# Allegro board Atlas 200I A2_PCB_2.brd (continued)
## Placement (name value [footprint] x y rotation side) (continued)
R2108  0*  [SR0402-TA]  107.07 40.51 0 top
R2109  0*  [SR0402-TA]  124.64 45.32 180 top
R2110  0  [SR0402-TA]  123.83 45.32 0 top
R2111  0*  [SR0402-TA]  124.64 46.66 180 top
R2112  0  [SR0402-TA]  123.83 46.66 0 top
R2121  0  [SR0402-TA]  107.88 39.18 180 top
R2122  0*  [SR0402-TA]  107.07 39.18 0 top
R2123  0  [SR0402-TA]  108.03 46.98 180 top
R2124  0*  [SR0402-TA]  107.21 46.98 0 top
R2125  0  [SR0402-TA]  108.03 45.64 180 top
R2126  0*  [SR0402-TA]  107.21 45.64 0 top
R2127  0  [SR0402-TA]  111.82 36.78 270 top
R2128  0*  [SR0402-TA]  111.82 35.97 90 top
R2129  0  [SR0402-TA]  113.16 36.78 270 top
R2130  0*  [SR0402-TA]  113.16 35.97 90 top
R2131  0  [SR0402-TA]  114.13 52.15 180 top
R2132  0*  [SR0402-TA]  113.32 52.15 0 top
R2133  0  [SR0402-TA]  114.13 50.81 180 top
R2134  0*  [SR0402-TA]  113.32 50.81 0 top
R2135  0  [SR0402-TA]  107.95 51.3 180 top
R2136  0*  [SR0402-TA]  107.14 51.3 0 top
R2137  0  [SR0402-TA]  107.95 49.96 180 top
R2138  0*  [SR0402-TA]  107.14 49.96 0 top
R2139  0  [SR0402-TA]  100.58 45.9 270 top
R2140  0*  [SR0402-TA]  100.58 45.08 90 top
R2141  1k  [SR0402-TA]  100.58 42.98 270 top
R2142  4.7k*  [SR0402-TA]  100.58 42.16 270 top
R2143  10k  [SR0402-TA]  97.17 46.8 0 top
R2201  5.6k  [SR0402-TA]  154.08 33.68 180 top
R2202  11.3K  [SR0402-TA]  154.89 31.85 90 top
R2203  10k*  [SR0402-TA]  151 31.03 90 top
R2204  10k  [SR0402-TA]  164.24 17.12 180 top
R2205  5.6k  [SR0402-TA]  141.85 27.91 90 top
R2206  11.3K  [SR0402-TA]  141.85 26.24 90 top
R2207  10k  [SR0402-TA]  138.94 27.91 270 top
R2208  10k  [SR0402-TA]  147.75 13.03 270 top
R2209  0  [SR0402-TA]  203.62 154.95 0 top
R2210  0  [SR0402-TA]  203.62 155.86 0 top
R2211  0  [SR0402-TA]  203.62 153.12 0 top
R2212  0  [SR0402-TA]  203.62 152.2 0 top
R2213  5.6k  [SR0402-TA]  236.73 173.35 90 top
R2214  11.3K  [SR0402-TA]  237.62 173.35 270 top
R2215  10k  [SR0402-TA]  238.51 173.35 270 top
R2216  10k  [SR0402-TA]  235.46 172.85 180 top
R2217  10k*  [SR0402-TA]  238.51 176.66 90 top
R2218  0  [SR0402-TA]  203.62 159.67 0 top
R2219  0  [SR0402-TA]  203.62 160.59 0 top
R2220  0  [SR0402-TA]  150.71 23.42 0 top
R2221  0  [SR0402-TA]  150.71 24.33 0 top
R2222  0  [SR0402-TA]  165.73 22.58 270 top
R2223  0  [SR0402-TA]  166.65 22.58 270 top
R2224  0  [SR0402-TA]  168.93 22.6 270 top
R2225  0  [SR0402-TA]  168.02 22.6 270 top
R2226  0  [SR0402-TA]  152.76 19.2 0 top
R2227  0  [SR0402-TA]  152.76 20.12 0 top
R2228  0  [SR0402-TA]  152.76 17.07 0 top
R2229  0  [SR0402-TA]  152.76 17.98 0 top
R2230  0  [SR0402-TA]  150.71 21.3 0 top
R2231  0  [SR0402-TA]  150.71 22.21 0 top
R2301  27k  [SR0402-TA]  121.92 191.52 180 top
R2302  100  [SR0402-TA]  121.92 192.53 0 top
R2305  100  [SR0402-TA]  128.14 195.33 270 top
R2306  100  [SR0402-TA]  128.14 193.17 90 top
R2307  4.7k  [SR0402-TA]  129.03 193.17 270 top
R2308  1k*  [SR0402-TA]  121.92 196.6 0 top
R2309  0  [SR0402-TA]  121.92 193.55 180 top
R2310  47k  [SR0402-TA]  121.92 195.58 180 top
R2317  4.7k  [SR0402-TA]  129.03 195.33 90 top
R2401  27k  [SR0402-TA]  96.8 184.12 180 top
R2402  100  [SR0402-TA]  96.8 185.14 0 top
R2403  100  [SR0402-TA]  103 187.83 180 top
R2404  100  [SR0402-TA]  103 184.78 180 top
R2405  4.7k  [SR0402-TA]  103 185.8 0 top
R2406  1k*  [SR0402-TA]  96.77 189.86 0 top
R2407  0  [SR0402-TA]  96.77 186.82 180 top
R2408  47k  [SR0402-TA]  96.77 187.83 180 top
R2417  4.7k  [SR0402-TA]  103 186.82 0 top
R2501  1.1k  [SR0603-TB]  195.45 17.14 0 top
R2502  1.1k  [SR0603-TB]  195.94 15.26 90 top
R2503  0  [SR0402-TA]  195.58 18.41 180 top
R2504  0  [SR0402-TA]  197.99 18.41 0 top
R2505  2.2k*  [SR0402-TA]  188.85 6.32 180 top
R2506  1.1k  [SR0603-TB]  197.99 17.14 180 top
R2507  1.1k  [SR0603-TB]  197.33 15.26 90 top
R2508  100k*  [SR0402-TA]  197.03 13 90 top
R2509  100k*  [SR0402-TA]  196.17 13 90 top
R2510  100k  [SR0402-TA]  188.34 14.17 0 top
R2511  100k  [SR0402-TA]  186.56 16.23 0 top
R2512  1k  [SR0402-TA]  181.61 23.42 270 top
R2513  2.49k  [SR0603B]  184.53 23.11 180 top
R2514  10k  [SR0402-TA]  180.21 23.8 180 top
R2515  4.7k  [SR0402-TA]  182.63 24.94 90 top
R2516  560  [SR0603-TB]  184.61 24.38 0 top
R2517  100k  [SR0402-TA]  177.42 18.29 90 top
R2518  100k  [SR0402-TA]  186.56 17.12 180 top
R2519  560  [SR0603-TB]  189.99 20.62 0 top
R2520  4.7k  [SR0402-TA]  189.74 21.97 0 top
R2521  10k  [SR0402-TA]  187.43 19.18 180 top
R2522  2.49k  [SR0603B]  188.93 18.62 90 top
R2523  1k  [SR0402-TA]  187.43 18.29 180 top
R2524  0  [SR0402-TA]  208.84 19.02 270 top
R2525  0  [SR0402-TA]  209.91 19.05 270 top
R2526  2.2k*  [SR0402-TA]  206.63 13.21 180 top
R2613  33  [SR0402-TA]  21.62 130.5 0 top
R2614  33  [SR0402-TA]  21.62 129.59 0 top
R2615  33  [SR0402-TA]  23.5 122.02 0 top
R2616  33  [SR0402-TA]  23.5 122.94 0 top
R2617  33  [SR0402-TA]  21.62 125.65 0 top
R2618  33  [SR0402-TA]  21.62 126.57 0 top
R2623  49.9  [SR0402-TA]  23.52 128.57 0 top
R2624  49.9  [SR0402-TA]  23.52 131.52 0 top
R2625  49.9  [SR0402-TA]  23.52 124.64 0 top
R2626  49.9  [SR0402-TA]  23.52 127.58 0 top
R2627  49.9  [SR0402-TA]  25.41 121.13 0 top
R2628  49.9  [SR0402-TA]  25.41 123.95 0 top
R2642  33  [SR0402-TA]  16.51 134.37 90 top
R2643  33  [SR0402-TA]  17.42 134.37 90 top
R2646  49.9  [SR0402-TA]  15.49 135.99 90 top
R2647  49.9  [SR0402-TA]  18.44 135.99 90 top
R2701  0  [SR0402-TA]  40.26 24.76 90 top
R2702  0  [SR0402-TA]  39.4 24.76 90 top
R2703  4.7k*  [SR0402-TA]  45.72 23.37 180 top
R2704  4.7k*  [SR0402-TA]  45.72 24.99 180 top
R2705  4.7k*  [SR0402-TA]  45.72 22.1 180 top
R2706  4.7k  [SR0402-TA]  47.63 23.37 0 top
R2707  4.7k  [SR0402-TA]  47.63 22.1 0 top
R2708  4.7k  [SR0402-TA]  47.63 24.99 0 top
R2709  0  [SR0402-TA]  170.94 31.24 90 top
R2710  0  [SR0402-TA]  170.94 33.78 90 top
R2711  4.7k  [SR0402-TA]  168.78 31.29 270 top
R2712  4.7k  [SR0402-TA]  175.77 19.76 270 top
R2713  4.7k  [SR0402-TA]  167.51 31.29 270 top
R2714  4.7k  [SR0402-TA]  174.65 19.76 270 top
R2715  4.7k  [SR0402-TA]  166.24 31.29 270 top
R2716  4.7k  [SR0402-TA]  173.53 19.76 270 top
R2717  4.7k  [SR0402-TA]  164.97 31.29 270 top
R2718  4.7k  [SR0402-TA]  172.42 19.76 270 top
R2719  4.7k  [SR0402-TA]  179.58 31.29 90 top
R2720  4.7k  [SR0402-TA]  178.31 31.29 90 top
R2721  4.7k  [SR0402-TA]  177.04 31.29 90 top
R2722  4.7k  [SR0402-TA]  175.77 31.29 90 top
R2723  4.7k  [SR0402-TA]  174.5 31.29 90 top
R2724  4.7k  [SR0402-TA]  173.25 37.77 90 top
R2725  4.7k  [SR0402-TA]  174.14 37.77 90 top
R2726  4.7k  [SR0402-TA]  173.23 31.29 90 top
R2727  1k  [SR0402-TA]  168.78 29.13 90 top
R2728  1k  [SR0402-TA]  175.73 17.5 90 top
R2729  1k  [SR0402-TA]  167.51 29.13 90 top
R2730  1k  [SR0402-TA]  174.62 17.5 90 top
R2731  1k  [SR0402-TA]  166.24 29.13 90 top
R2732  1k  [SR0402-TA]  173.51 17.5 90 top
R2733  1k  [SR0402-TA]  164.97 29.13 90 top
R2734  1k  [SR0402-TA]  172.4 17.5 90 top
R2735  1k  [SR0402-TA]  179.58 33.83 270 top
R2736  1k  [SR0402-TA]  178.31 33.83 270 top
R2737  1k  [SR0402-TA]  177.04 33.83 270 top
R2738  1k  [SR0402-TA]  175.77 33.83 270 top
R2739  1k  [SR0402-TA]  174.5 33.83 270 top
R2740  1k  [SR0402-TA]  173.63 36.4 180 top
R2741  1k  [SR0402-TA]  175.46 38.23 180 top
R2742  1k  [SR0402-TA]  173.23 33.83 270 top
R2743  4.7k*  [SR0402-TA]  172.09 31.24 90 top
R2744  4.7k*  [SR0402-TA]  170.18 19.79 270 top
R2745  4.7k*  [SR0402-TA]  171.3 19.79 270 top
R2746  1k  [SR0402-TA]  171.29 17.5 90 top
R2747  1k  [SR0402-TA]  170.18 17.5 90 top
R2748  1k  [SR0402-TA]  171.96 33.83 270 top
R2749  4.7k  [SR0402-TA]  3.8 100.99 90 top
R2750  33  [SR0402-TA]  6.3 109.93 270 top
R2751  33  [SR0402-TA]  5.38 109.93 270 top
R2752  33  [SR0402-TA]  4.82 100.99 270 top
R2753  33  [SR0402-TA]  5.71 100.99 270 top
R2754  4.7k  [SR0402-TA]  133.78 76.75 90 top
R2755  4.7k  [SR0402-TA]  131.83 78.54 270 top
R2758  0  [SR0402-TA]  93.44 131.98 180 top
R2759  33  [SR0402-TA]  85.52 131.1 90 top
R2760  33  [SR0402-TA]  84.51 131.1 90 top
R2761  0  [SR0402-TA]  86.54 131.1 90 top
R2762  33  [SR0402-TA]  88.06 131.1 90 top
R2763  0  [SR0402-TA]  89.59 131.1 90 top
R2776  0  [SR0402-TA]  24.31 21.61 180 top
R2777  0  [SR0402-TA]  22.23 26.92 0 top
R2778  0  [SR0402-TA]  36.53 28.63 180 top
R2779  0  [SR0402-TA]  20.32 25.53 270 top
R2780  0*  [SR0402-TA]  20.32 27.66 270 top
R2781  1k*  [SR0402-TA]  22.23 28.07 0 top
R2782  33  [SR0402-TA]  24.26 28.07 0 top
R2783  33  [SR0402-TA]  41.02 27.43 270 top
R2784  4.7k*  [SR0402-TA]  40.01 27.43 90 top
R2801  33  [SR0402-TA]  188.6 49.4 0 top
R2802  33  [SR0402-TA]  190.63 39.75 180 top
R2803  4.7k*  [SR0402-TA]  195.96 59.05 270 top
R2804  4.7k  [SR0402-TA]  194.82 70.48 180 top
R2805  4.7k  [SR0402-TA]  193.29 59.16 90 top
R2806  33  [SR0402-TA]  194.69 59.44 0 top
R2807  33  [SR0402-TA]  192.91 38.76 0 top
R2808  33  [SR0402-TA]  188.6 50.55 0 top
R2809  4.7k*  [SR0402-TA]  190.63 54.61 180 top
R2810  4.7k*  [SR0402-TA]  192.02 59.16 90 top
R2811  200  [SR0402-TA]  205.74 31.37 0 top
R2812  33  [SR0402-TA]  207.14 56.51 270 top
R2813  33  [SR0402-TA]  199.01 56.54 270 top
R2814  150k  [SR0402-TA]  189.48 32.03 90 top
R2815  30k  [SR0402-TA]  189.48 34.39 90 top
R2816  10k  [SR0402-TA]  190.5 34.31 90 top
R2817  20k  [SR0402-TA]  190.5 32.03 90 top
R2818  10k  [SR0402-TA]  191.52 32.03 90 top
R2819  10k  [SR0402-TA]  191.52 34.31 90 top
R2820  10k  [SR0402-TA]  188.47 32.03 90 top
R2821  10k  [SR0402-TA]  188.47 34.39 90 top
R2822  10k  [SR0402-TA]  192.53 34.31 90 top
R2823  20k  [SR0402-TA]  192.53 32.03 90 top
R2824  10k  [SR0402-TA]  193.55 34.31 90 top
R2825  10k  [SR0402-TA]  193.55 32.03 90 top
R2826  0*  [SR0402-TA]  188.98 48.06 270 top
R2827  0  [SR0402-TA]  197.87 36.32 270 top
R2828  4.7k  [SR0402-TA]  186.44 45.72 180 top
R2829  4.7k*  [SR0402-TA]  188.34 45.72 0 top
R2830  4.7k  [SR0402-TA]  196.88 59.05 270 top
R2831  0  [SR0402-TA]  194.56 34.19 270 top
R2832  33  [SR0402-TA]  206.12 54.23 90 top
R2833  0  [SR0402-TA]  199.52 38.61 270 top
R2834  33  [SR0402-TA]  202.06 56.51 90 top
R2835  33  [SR0402-TA]  205.11 56.51 90 top
R2836  33  [SR0402-TA]  206.15 56.49 90 top
R2837  0  [SR0402-TA]  203.2 38.48 270 top
R2838  0  [SR0402-TA]  198.5 38.61 270 top
R2839  33  [SR0402-TA]  204.09 54.23 90 top
R2840  0  [SR0402-TA]  196.95 36.32 270 top
R2841  33  [SR0402-TA]  202.06 54.23 90 top
R2842  33  [SR0402-TA]  200.03 54.23 90 top
R2843  33  [SR0402-TA]  199.01 54.23 90 top
R2844  0  [SR0402-TA]  203.43 36.19 270 top
R2845  0  [SR0402-TA]  190.63 53.59 180 top
R2846  33  [SR0402-TA]  205.11 54.23 90 top
R2847  0  [SR0402-TA]  203.07 56.51 90 top
R2848  33  [SR0402-TA]  204.09 56.51 90 top
R2849  33  [SR0402-TA]  178.15 40.49 270 top
R2850  33  [SR0402-TA]  179.01 40.49 90 top
R2851  33  [SR0402-TA]  179.86 40.49 90 top
R2852  33  [SR0402-TA]  180.72 40.49 90 top
R2853  0  [SR0402-TA]  196.6 32.16 0 top
R2854  0  [SR0402-TA]  196.6 33.01 0 top
R2855  0  [SR0402-TA]  207.44 36.19 90 top
R2856  0  [SR0402-TA]  192.91 40.77 0 top
R2857  0  [SR0402-TA]  209.42 40 180 top
R2858  0  [SR0402-TA]  201.04 54.23 270 top
R2859  0  [SR0402-TA]  206.58 36.19 90 top
R2860  0  [SR0402-TA]  201.04 56.51 270 top
R2861  0  [SR0402-TA]  184.4 42.8 0 top
R2862  0  [SR0402-TA]  196.6 33.87 0 top
R2863  0  [SR0402-TA]  186.44 46.61 0 top
R2864  0  [SR0402-TA]  184.4 44.83 0 top
R2865  0  [SR0402-TA]  184.4 43.81 0 top
R2866  0  [SR0402-TA]  184.4 41.78 0 top
R2867  33  [SR0402-TA]  188.34 44.7 180 top
R2868  33  [SR0402-TA]  191.77 41.78 180 top
R2869  0  [SR0402-TA]  192.91 44.83 180 top
R2870  0  [SR0402-TA]  192.91 43.81 180 top
R2871  33  [SR0402-TA]  192.91 42.8 180 top
R2872  33  [SR0402-TA]  186.41 42.6 270 top
R2873  0  [SR0402-TA]  190.63 40.64 0 top
R2874  0  [SR0402-TA]  188.34 42.8 0 top
R2875  33  [SR0402-TA]  192.91 54.61 0 top
R2876  33  [SR0402-TA]  192.91 53.59 180 top
R2878  33  [SR0402-TA]  191.46 56.51 270 top
R2879  33  [SR0402-TA]  195.33 38.35 270 top
R2881  33  [SR0402-TA]  5.23 33.89 0 top
R2882  33  [SR0402-TA]  7.01 33.89 180 top
R2883  33  [SR0402-TA]  132.72 27.98 180 top
R2884  33  [SR0402-TA]  132.18 25.63 270 top
R2885  33  [SR0402-TA]  24.33 94.92 0 top
R2886  33  [SR0402-TA]  24.33 95.86 0 top
R2887  4.7k  [SR0402-TA]  26.75 85.04 270 top
R2888  4.7k*  [SR0402-TA]  24.21 85.04 270 top
R2889  4.7k  [SR0402-TA]  25.48 85.04 270 top
R2890  1k*  [SR0402-TA]  26.75 82.5 90 top
R2891  4.7k  [SR0402-TA]  6.2 44.2 180 top
R2892  4.7k*  [SR0402-TA]  10.41 44.2 180 top
R2893  4.7k*  [SR0402-TA]  8.13 44.2 0 top
R2894  1k*  [SR0402-TA]  6.2 43.18 0 top
R2895  1k  [SR0402-TA]  10.41 43.18 0 top
R2896  1k  [SR0402-TA]  8.13 43.18 180 top
R2897  1k  [SR0402-TA]  24.21 82.5 90 top
R2898  1k*  [SR0402-TA]  25.48 82.5 90 top
R2899  1k*  [SR0402-TA]  122.52 28.22 0 top
R2921  33  [SR0402-TA]  62.31 152.78 90 top
R2922  33  [SR0402-TA]  61.24 143.41 90 top
R2923  33  [SR0402-TA]  77.67 143.69 90 top
R2928  33  [SR0402-TA]  67.64 143.36 90 top
R2929  33  [SR0402-TA]  66.75 143.36 90 top
R2930  33  [SR0402-TA]  65.86 143.36 90 top
R2931  33  [SR0402-TA]  64.95 143.36 90 top
R2932  4.7k  [SR0402-TA]  87.27 149.33 180 top
R2933  4.7k*  [SR0402-TA]  85.21 143.71 90 top
R2934  33  [SR0402-TA]  81.79 143.66 90 top
R2935  33  [SR0402-TA]  82.64 143.66 90 top
R2936  33  [SR0402-TA]  83.5 143.66 90 top
R2937  33  [SR0402-TA]  84.35 143.66 90 top
R2938  33  [SR0402-TA]  83.31 151.13 90 top
R2939  33  [SR0402-TA]  84.33 151.13 90 top
R2940  33  [SR0402-TA]  87.27 151.04 0 top
R2941  33  [SR0402-TA]  87.27 150.19 0 top
R2942  4.7k  [SR0402-TA]  68.66 150.24 180 top
R2943  4.7k*  [SR0402-TA]  69.31 143.16 180 top
R2945  33  [SR0402-TA]  80.91 143.66 90 top
R2946  33  [SR0402-TA]  63.2 143.38 90 top
R2947  33  [SR0402-TA]  79.76 143.66 90 top
R2948  33  [SR0402-TA]  62.31 143.38 90 top
R2949  33  [SR0402-TA]  78.74 143.66 90 top
R2952  33  [SR0402-TA]  63.2 152.78 90 top
R2953  33  [SR0402-TA]  81.03 151.76 180 top
R2954  33  [SR0402-TA]  81.03 150.75 180 top
R2955  33  [SR0402-TA]  77.72 148.59 180 top
R2956  33  [SR0402-TA]  77.72 147.58 180 top
R2973  4.7k*  [SR0402-TA]  62.31 141.1 90 top
R2974  4.7k*  [SR0402-TA]  59.84 141.1 90 top
R2975  4.7k*  [SR0402-TA]  78.23 141.45 90 top
R2976  4.7k*  [SR0402-TA]  76.12 143.69 270 top
R2983  1k  [SR0402-TA]  26.82 130.87 180 top
R2984  4.7k  [SR0402-TA]  26.82 129.77 180 top
R2985  1k  [SR0402-TA]  22.99 134.75 90 top
R2986  2k*  [SR0402-TA]  21.7 134.17 180 top
R2988  1k  [SR0402-TA]  26.82 131.73 180 top
R2990  4.7k*  [SR0402-TA]  60.22 154.84 0 top
R2991  4.7k*  [SR0402-TA]  59.94 152.81 90 top
R2992  4.7k*  [SR0402-TA]  77.72 145.87 180 top
R2993  4.7k*  [SR0402-TA]  76.93 151.08 270 top
R2997  4.7k  [SR0402-TA]  63.2 141.1 90 top
R2999  4.7k  [SR0402-TA]  65.86 141.1 90 top
R3001  10k*  [SR0402-TA]  25.76 177.01 90 top
R3002  0  [SR0402-TA]  30.28 171.32 0 top
R3003  30k  [SR0402-TA]  24.51 164.12 180 top
R3004  2.2  [SR0805-TB]  17.12 185.37 90 top
R3005  2.2  [SR0805-TB]  18.9 185.37 90 top
R3006  10k  [SR0402-TA]  26.29 175.51 0 top
R3007  0*  [SR0402-TA]  30.4 174.5 180 top
R3008  10k*  [SR0402-TA]  30.28 172.26 180 top
R3009  10  [SR0402-TA]  14.35 172.47 180 top
R3010  4.7k  [SR0402-TA]  24.51 165.07 0 top
R3011  10  [SR0402-TA]  4.95 144.27 90 top
R3012  10  [SR0402-TA]  3.94 144.27 270 top
R3013  1k  [SR0402-TA]  6.22 144.27 90 top
R3014  1k  [SR0402-TA]  3.81 134.53 0 top
R3015  1k  [SR0402-TA]  5.52 134.53 180 top
R3016  33  [SR0402-TA]  7.98 137.44 180 top
R3017  33  [SR0402-TA]  7.98 136.42 180 top
R3018  3m  [SR2512B-TF]  19.46 179.15 270 top
R3019  3m  [SR2512B-TF]  15.42 179.15 270 top
R3020  15k  [SR0402-TA]  26.72 165.05 90 top
R3021  10k  [SR0402-TA]  27.64 165.05 270 top
R3022  0  [SR0402-TA]  25.01 167.67 90 top
R3023  10k  [SR0402-TA]  22 166.06 270 top
R3102  4.7k*  [SR0402-TA]  153.54 66.47 180 top
R3103  1k  [SR0402-TA]  151.92 66.7 270 top
R3104  20k  [SR0402-TA]  151.51 63.33 180 top
R3105  33  [SR0402-TA]  151.51 62.48 0 top
R3106  33  [SR0402-TA]  96.44 165.15 180 top
R3107  10k  [SR0402-TA]  98.48 166.17 180 top
R3108  4.7k  [SR0402-TA]  98.48 164.13 180 top
R3109  27k  [SR0402-TA]  96.48 162.05 0 top
R3110  47k  [SR0402-TA]  96.48 161.04 180 top
R3111  49.9  [SR0402-TA]  96.44 167.18 0 top
R3112  301  [SR0402-TA]  96.44 166.17 180 top
R3113  2.2  [SR0402-TB]  106.38 161.64 0 top
R3114  47k  [SR0402-TA]  105.11 163.78 270 top
R3115  1k  [SR0402-TA]  98.48 167.18 0 top
R3116  33  [SR0402-TA]  107.19 179.53 90 top
R3117  10k  [SR0402-TA]  107.19 177.88 90 top
R3118  27k  [SR0402-TA]  107.14 175.95 90 top
R3119  47k  [SR0402-TA]  108.15 175.95 270 top
R3120  330  [SR0402-TA]  109.17 179.53 90 top
R3121  330  [SR0402-TA]  108.2 179.53 90 top
R3122  2k  [SR0402-TA]  108.2 177.88 270 top
R3123  1k  [SR0402-TA]  112.5 170.43 180 top
R3124  33  [SR0402-TA]  110.9 173.42 90 top
R3125  4.7k  [SR0402-TA]  109.88 173.42 90 top
R3126  33  [SR0402-TA]  111.94 182.09 90 top
R3127  10k  [SR0402-TA]  113.18 181.41 180 top
R3128  27k  [SR0402-TA]  115.09 181.13 180 top
R3129  47k  [SR0402-TA]  115.09 182.04 0 top
R3130  1k  [SR0402-TA]  113.18 182.3 0 top
R3131  2k  [SR0402-TA]  113.18 183.36 0 top
R3132  200  [SR0402-TA]  113.18 184.25 180 top
R3134  1k  [SR0402-TA]  120.83 184.73 270 top
R3135  33  [SR0402-TA]  113.82 185.95 180 top
R3136  4.7k  [SR0402-TA]  117.27 187.15 0 top
R3137  1k  [SR0402-TA]  112.5 169.44 0 top
R3138  1k  [SR0402-TA]  119.81 184.73 90 top
R3201  20k  [SR0402-TA]  162.65 64.06 0 top
R3202  1k*  [SR0402-TA]  165.45 69.39 90 top
R3203  33  [SR0402-TA]  156.6 60.07 270 top
R3204  20k  [SR0402-TA]  156.54 58.69 180 top
R3205  1k  [SR0402-TA]  158.72 60.22 90 top
R3206  4.7k*  [SR0402-TA]  158.32 58.69 0 top
R3208  2.49k  [SR0402-TA]  26.06 47.45 270 top
R3210  1k*  [SR0402-TA]  22.12 50.27 270 top
R3211  33  [SR0402-TA]  23.83 47.47 90 top
R3213  4.7k  [SR0402-TA]  25.48 54 90 top
R3214  2k  [SR0402-TA]  26.96 47.45 270 top
R3216  10k*  [SR0402-TA]  197.87 28.96 0 top
R3217  10k  [SR0402-TA]  197.87 27.94 0 top
R3218  10M  [SR0402-TA]  194.26 22.5 90 top
R3219  10M  [SR0402-TA]  194.72 21.16 180 top
R3220  10M  [SR0402-TA]  193.24 22.5 90 top
R3221  10M*  [SR0402-TA]  191.87 22.3 180 top
R3222  240  [SR0402-TA]  167.77 69.37 90 top
R3223  200  [SR0402-TA]  169.08 69.39 270 top
R3301  10k  [SR0402-TA]  213.61 22.03 180 top
R3302  20k  [SR0402-TA]  213.61 23.05 180 top
R3303  1k  [SR0402-TA]  210.93 22.64 90 top
R3304  2k  [SR0402-TA]  217.86 21.72 0 top
R3305  2k  [SR0402-TA]  180.87 38.53 180 top
R3306  10k  [SR0402-TA]  181.76 35.43 0 top
R3307  2k  [SR0402-TA]  149.66 58.7 270 top
R3308  10k  [SR0402-TA]  182.37 33.83 270 top
R3309  10k  [SR0402-TA]  181.36 33.83 90 top
R3310  1k  [SR0402-TA]  210.07 22.64 90 top
R3401  3k  [SR0402-TA]  11.68 54.61 270 top
R3403  4.7k  [SR0402-TA]  19.05 93.03 0 top
R3404  4.7k*  [SR0402-TA]  17.15 93.03 0 top
R3405  4.7k  [SR0402-TA]  18.64 86.85 90 top
R3406  4.7k  [SR0402-TA]  17.11 54.93 180 top
R3407  0  [SR0402-TA]  10.67 54.61 90 top
R3408  4.7k  [SR0402-TA]  11.68 46.99 270 top
R3409  330*  [SR0402-TA]  11.74 52.58 270 top
R3410  4.7k*  [SR0402-TA]  13.08 45.97 180 top
R3411  0*  [SR0402-TA]  10.03 52.58 270 top
R3412  1k  [SR0402-TA]  19.89 80.12 90 top
R3413  1k  [SR0402-TA]  21.01 80.14 90 top
R3414  0*  [SR0402-TA]  11.68 48.77 270 top
R3415  33*  [SR0402-TA]  11.68 50.67 270 top
R3416  15k  [SR0402-TA]  10.88 52.58 270 top
R3419  33  [SR0402-TA]  20.14 90.08 90 top
R3420  0  [SR0402-TA]  26.8 80.14 90 top
R3422  4.7k  [SR0402-TA]  40.32 19.75 270 top
R3423  4.7k  [SR0402-TA]  16.22 89.22 90 top
R3424  4.7k  [SR0402-TA]  17.78 86.85 270 top
R3425  100  [SR0402-TA]  39.79 18.12 180 top
R3426  150  [SR0402-TA]  19.62 86.85 270 top
R3502  2k  [SR0402-TA]  34.69 149.83 270 top
R3503  20k  [SR0402-TA]  32.89 150.88 270 top
R3504  10k  [SR0402-TA]  34.31 151.13 180 top
R3505  2k  [SR0402-TA]  30.61 150.88 270 top
R3506  2k  [SR0402-TA]  29.59 150.88 90 top
R3507  240  [SR2512-TE]  98.74 142.11 0 top
R3508  240  [SR2512-TE]  43.18 94.42 270 top
R3509  240  [SR2512-TE]  54.75 130.17 180 top
R3510  240  [SR2512-TE]  90.26 138.18 180 top
R3511  240  [SR2512-TE]  93.42 134.37 180 top
R3512  240  [SR2512-TE]  80.96 138.18 0 top
R3513  240  [SR2512-TE]  72.07 138.18 0 top
R3514  240  [SR2512-TE]  98.69 138.18 180 top
R3515  240  [SR2512-TE]  104.84 140.5 90 top
R3516  240  [SR2512-TE]  39.37 111.89 90 top
R3517  240  [SR2512-TE]  27.94 103.24 270 top
R3518  240  [SR2512-TE]  111.27 134.37 0 top
R3519  240  [SR2512-TE]  115.95 58.55 180 top
R3520  240  [SR2512-TE]  43.18 76.58 90 top
R3521  240  [SR2512-TE]  80.2 54.84 180 top
R3522  240  [SR2512-TE]  62.33 50.8 180 top
R3523  240  [SR2512-TE]  80.2 50.8 180 top
R3524  240  [SR2512-TE]  39.37 94.42 90 top
R3525  240  [SR2512-TE]  35.56 103.24 270 top
R3526  240  [SR2512-TE]  45.42 130.05 180 top
R3527  240  [SR2512-TE]  84.58 134.37 0 top
R3528  240  [SR2512-TE]  74.93 134.37 180 top
R3529  240  [SR2512-TE]  66.1 133.92 0 top
R3530  240  [SR2512-TE]  98.08 54.84 0 top
R3531  240  [SR2512-TE]  71.26 50.8 180 top
R3532  240  [SR2512-TE]  71.26 54.84 180 top
R3533  240  [SR2512-TE]  62.33 54.84 0 top
R3534  240  [SR2512-TE]  62.33 58.55 0 top
R3536  2k  [SR0402-TA]  28.65 135.6 270 top
R3537  20k  [SR0402-TA]  28.45 138.43 270 top
R3538  10k  [SR0402-TA]  28.47 137.01 180 top
R3539  2k  [SR0402-TA]  22.48 137.75 0 top
R3540  2k  [SR0402-TA]  22.48 139.57 180 top
R3541  240  [SR2512-TE]  98.08 58.55 180 top
R3542  240  [SR2512-TE]  31.75 66.95 270 top
R3543  240  [SR2512-TE]  124.89 58.8 0 top
R3544  240  [SR2512-TE]  39.37 66.93 270 top
R3545  240  [SR2512-TE]  43.18 66.93 270 top
R3546  240  [SR2512-TE]  39.37 76.58 90 top
R3547  240  [SR2512-TE]  35.56 66.95 270 top
R3548  240  [SR2512-TE]  31.75 85.62 270 top
R3549  240  [SR2512-TE]  71.26 58.55 0 top
R3550  240  [SR2512-TE]  35.56 76.58 90 top
R3551  240  [SR2512-TE]  44.45 58.55 0 top
R3552  240  [SR2512-TE]  31.75 76.58 270 top
R3553  240  [SR2512-TE]  44.45 54.84 0 top
R3554  240  [SR2512-TE]  44.45 50.8 0 top
R3555  240  [SR2512-TE]  27.94 66.95 90 top
R3556  240  [SR2512-TE]  53.39 50.8 180 top
R3557  240  [SR2512-TE]  53.39 54.84 180 top
R3558  240  [SR2512-TE]  89.14 54.84 180 top
R3559  240  [SR2512-TE]  35.56 85.62 90 top
R3560  240  [SR2512-TE]  89.14 58.55 180 top
R3561  240  [SR2512-TE]  134.85 31.09 0 top
R3562  240  [SR2512-TE]  151.51 49.91 270 top
R3563  240  [SR2512-TE]  151.51 41.15 90 top
R3564  240  [SR2512-TE]  143.35 30.85 180 top
R3565  240  [SR2512-TE]  125.98 31.87 180 top
R3566  240  [SR2512-TE]  135.57 58.57 0 top
R3567  240  [SR2512-TE]  144.55 58.57 180 top
R3568  240  [SR2512-TE]  90.31 142.11 180 top
R3569  240  [SR2512-TE]  45.42 137.79 180 top
R3570  240  [SR2512-TE]  43.19 103.24 90 top
R3571  240  [SR2512-TE]  43.18 111.89 90 top
R3572  240  [SR2512-TE]  31.75 94.42 90 top
R3573  240  [SR2512-TE]  39.37 103.24 90 top
R3574  240  [SR2512-TE]  45.42 133.86 180 top
R3575  240  [SR2512-TE]  54.75 137.79 0 top
R3576  240  [SR2512-TE]  35.56 111.89 270 top
R3577  240  [SR2512-TE]  102.36 134.37 0 top
R3578  240  [SR2512-TE]  31.75 103.24 90 top
R3579  240  [SR2512-TE]  54.75 133.98 0 top
R3580  240  [SR2512-TE]  53.39 58.55 180 top
R3581  240  [SR2512-TE]  80.2 58.55 180 top
R3582  240  [SR2512-TE]  35.56 94.42 90 top
R3583  240  [SR2512-TE]  63.44 137.79 0 top
R3584  240  [SR2512-TE]  128.27 46.47 90 top
R3585  240  [SR2512-TE]  128.27 38.04 270 top
R3586  240  [SR2512-TE]  117.48 31.74 0 top
R3587  240  [SR2512-TE]  124.89 55.1 180 top
R3588  240  [SR2512-TE]  102.98 39.58 270 top
R3589  240  [SR2512-TE]  107.01 58.55 180 top
R3590  240  [SR2512-TE]  102.92 48.26 90 top
R3591  240  [SR2512-TE]  107.01 54.84 180 top
R3592  240  [SR2512-TE]  115.95 54.84 0 top
R3601  330  [SR0402-TA]  54.23 17.4 180 top
R3602  330  [SR0402-TA]  51.31 17.4 0 top
R3603  1k  [SR0402-TA]  49.4 23.24 270 top
R3604  1k  [SR0402-TA]  52.71 23.24 90 top
R3605  1k  [SR0402-TA]  54.1 23.75 0 top
R3606  1k  [SR0402-TA]  50.8 23.75 0 top
R3607  4.7k  [SR0402-TA]  36.89 19.67 270 top
R3608  240  [SR0402-TA]  70.74 6.1 90 top
R3609  240  [SR0402-TA]  71.76 6.1 90 top
R3611  1k  [SR0402-TA]  72.34 11.61 90 top
R3613  4.7k  [SR0402-TA]  18.42 25.15 0 top
R3614  330  [SR0402-TA]  60.96 17.4 180 top
R3615  330  [SR0402-TA]  58.04 17.4 0 top
R3616  1k  [SR0402-TA]  56.52 23.37 270 top
R3617  1k  [SR0402-TA]  60.2 23.37 90 top
R3618  1k  [SR0402-TA]  61.6 23.88 0 top
R3619  1k  [SR0402-TA]  57.91 23.88 0 top
R3620  100  [SR0402-TA]  37.53 18.12 0 top
R3621  100  [SR0402-TA]  18.42 26.16 180 top
R3801  100  [SR0402-TA]  58.17 25.27 90 top
RT1  RT  [SF1913]  128.02 190.12 180 top
RT2  RT  [SF1913]  103.51 190.52 0 top
RV1501  NONE  [SR3-4926B]  153.37 194.18 180 top
RV1502  NONE  [SR3-4926B]  178.82 194.18 180 top
RV1601  NONE  [SR3-4926B]  222.38 194.18 0 top
S3401  NONE  [RTSW4-RG]  36.25 11.07 0 top
S3601  NONE  [RTSW4-RG]  25.8 11.07 0 top
S3602  NONE  [RTSW4-RG]  15.3 18.37 0 top
SG1  0  [GND_SINGLE_4]  180.09 17.78 180 top
T1  -99.999999H*  [SL4-0102]  152.5 82.04 180 top
T1501  NONE  [STFM24-40-280]  146.69 183.16 0 top
T1502  NONE  [STFM24-40-280]  208.08 183.26 0 top
T1503  NONE  [STFM24-40-280]  179.88 183.26 0 top
T1504  NONE  [STFM24-40-280]  164.01 183.26 0 top
T1601  NONE  [STFM24-40-280]  227.33 183.26 0 top
T1602  -99.999999H*  [SL4-0102]  88.15 169.46 90 top
T2201  -99.999999H*  [SL4-0102]  203.62 155.41 270 top
T2202  -99.999999H*  [SL4-0102]  203.62 152.66 270 top
T2203  -99.999999H*  [SL4-0102]  203.62 160.13 270 top
T2204  -99.999999H*  [SL4-0102]  150.71 23.87 270 top
T2205  -99.999999H*  [SL4-0102]  166.19 22.58 180 top
T2206  -99.999999H*  [SL4-0102]  168.47 22.6 180 top
T2207  -99.999999H*  [SL4-0102]  152.76 19.66 270 top
T2208  -99.999999H*  [SL4-0102]  152.76 17.53 270 top
T2209  -99.999999H*  [SL4-0102]  150.71 21.75 270 top
TP1  NONE  [TP45_45-SMD]  186.69 48.77 90 top
TP2  NONE  [TP45_45-SMD]  188.09 37.54 90 top
TP3  NONE  [TP45_45-SMD]  188.09 35.94 270 top
TP4  NONE  [TP45_45-SMD]  182.37 53.97 270 top
TP5  NONE  [TP45_45-SMD]  190.25 35.94 270 top
TP6  *  [TP45_45-SMD]  186.46 44.5 270 top
TP7  none  [TP50-SMD-OSP]  215.9 188.59 0 top
TP8  none  [TP50-SMD-OSP]  219.71 188.59 0 top
TP9  NONE  [TP2-50-5MIL]  6.22 22.33 0 top
TP10  NONE  [TP2-50-5MIL]  237.82 189.26 270 top
TP11  NONE  [GND12]  188.09 79.12 180 top
TP12  NONE  [GND12]  188.09 81.03 90 top
TP13  NONE  [TP50-SMD]  226.7 33.27 180 bottom
TP14  NONE  [TP50-SMD]  226.7 37.34 180 bottom
TP15  NONE  [TP50-SMD]  220.73 31.8 180 bottom
TP16  NONE  [TP50-SMD]  220.73 34.16 180 bottom
TP17  NONE  [TP50-SMD]  218.69 41.53 270 bottom
TP18  NONE  [TP50-SMD]  222.38 41.53 270 bottom
TP19  NONE  [TP50-SMD]  224.71 48.84 180 bottom
TP20  NONE  [TP50-SMD]  224.79 41.53 270 bottom
TP21  NONE  [TP50-SMD]  238.56 25.48 180 bottom
TP22  NONE  [TP50-SMD]  216.28 41.53 270 bottom
TP23  NONE  [TP45_45-SMD]  186.69 52.07 0 top
TP24  NONE  [TP45_45-SMD]  190.25 37.54 90 top
TP25  NONE  [TP50-SMD]  15.88 189.23 90 bottom
TP26  NONE  [TP50-SMD]  15.88 187.32 90 bottom
TP29  NONE  [TP50-SMD]  24.77 189.23 180 bottom
TP34  NONE  [TP50-SMD]  24.77 187.32 90 bottom
U1  NONE  [MLF36A-065-0707L]  168.01 63.63 90 top
U2  NONE  [SOP4-100-256B]  87.68 180.12 270 top
U3  NONE  [BGA208-32-1515A]  200.66 46.35 0 top
U4  NONE  [SOP8-50-154C]  181.84 19.48 270 top
U5  NONE  [SOP8-50-154C]  198.72 24.45 270 top
U6  NONE  [QFP128HG-040-1414L]  122.78 147.78 180 top
U7  NONE  [SOP4-100-256B]  87.68 191.55 270 top
U8  NONE  [SOP4-100-256B]  87.68 174.4 270 top
U9  NONE  [BGA153-20-1414A]  47.35 150.7 90 top
U10  NONE  [SOP8-20-91C]  18.24 90.08 0 top
U11  NONE  [MLF36A-065-0707L]  176.45 63.63 270 top
U12  NONE  [SOP4-100-256B]  87.68 185.83 270 top
U13  SRV05-4  [SOT23-6A]  125.48 194.18 270 top
U14  SRV05-4  [SOT23-6A]  99.82 186.69 270 top
U15  NONE  [MLF24D-050-0604L]  162.94 48.77 90 top
U16  NONE  [MLF24D-050-0604L]  162.56 39.52 90 top
U17  NONE  [SOP14-26-173C]  29.85 24.51 90 top
U301  NONE  [MLF64AG-050-0909L]  13.94 127.08 270 top
U701  SRV05-4  [SOT23-6A]  100.33 33.02 90 top
U1001  NONE  [SOT23-3]  207.01 21.21 270 top
U1002  NONE  [SOP24-26-173A]  178.64 45.89 0 top
U1201  NONE  [MLF48A-040-0606L]  144.26 73.37 180 top
U1301  NONE  [SOP8-20-91C]  121.08 130.56 270 top
U1401  NONE  [MLF7-045-0202L]  99.85 149.81 270 top
U1601  NONE  [SOP16-26-208-255]  186.23 154.76 270 top
U1602  NONE  [SOP14-50-150]  83.79 157.33 0 top
U1603  NONE  [SOP8-50-150B]  76 159.63 0 top
U1604  NONE  [SOP8-50-154C]  91.44 159.89 0 top
U1901  SRV05-4  [SOT23-6A]  125.89 22.27 90 top
U1902  SRV05-4  [SOT23-6A]  117.65 22.27 90 top
U2001  *  [SOP8-50-208]  63.25 45.77 90 top
U2002  *  [MLF76Q-040-0909L]  138.56 44.22 180 top
U2003  NONE  [SOP8-26-118C]  133.26 72.11 180 top
U2101  NONE  [MLF76L-040-0909L]  116.29 43.27 270 top
U2201  NONE  [MLF6C-065-0202L]  152.96 30.78 90 top
U2202  NONE  [MLF6C-065-0202L]  139.85 25.35 90 top
U2203  NONE  [MLF6C-065-0202L]  236.6 176.02 0 top
U2205  SRV05-4  [SOT23-6A]  155.45 22.81 270 top
U2206  SRV05-4  [SOT23-6A]  208.39 160.14 270 top
U2701  NONE  [MLF8A-050-0203L]  42.6 23.49 90 top
U2703  NONE  [SOP24-26-173A]  173.94 25.11 0 top
U2704  NONE  [SOP8-26-118C]  5.91 105.61 180 top
U2801  NONE  [SOP8-50-208]  195.2 65.02 0 top
U2802  NONE  [SOT23-3]  205.23 33.91 0 top
U2803  NONE  [SOP8-50-154C]  127.73 26.96 90 top
U2804  NONE  [SOP8-50-154C]  7.24 38.33 0 top
U2805  NONE  [SOP8-50-154C]  25.6 90.12 180 top
U2903  NONE  [MLF24D-050-0604L]  82.8 147.34 180 top
U2904  NONE  [MLF24D-050-0604L]  64.44 147.34 180 top
U3001  NONE  [SOP10-20-118]  27.43 170.05 0 top
U3002  NONE  [SOP10-20-124A]  4.78 138.33 0 top
U3101  NONE  [MLF14A-050-0404L]  102.16 162.51 180 top
U3102  JW5043SOTI  [SOT666-6]  104.15 176.71 270 top
U3103  JW5043SOTI  [SOT666-6]  114.33 178.59 0 top
U3201  NONE  [MLF20J-050-0404L]  25.86 50.62 0 top
U3202  NONE  [SBAT2-3209]  82.13 38.79 0 top
U3401  NONE  [SOT23-5]  25.4 76.96 180 top
U3402  NONE  [SOP8-50-154M]  15.08 50.48 180 top
X1  25MHz  [HSX4-0302B]  210.57 47.83 90 top
X2  12MHz  [SX4-0303K]  93.47 50.02 0 top
X3  48MHz  [HSX4-0302B]  5.51 127.26 270 top
X1201  25MHz  [HSX4-0302B]  152.65 71.37 0 top
X1301  25MHz  [HSX4-0302B]  130.56 133.17 180 top
X2001  25MHz*  [HSX4-0302B]  148.08 38.61 270 top

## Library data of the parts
C1 C45 C53 C79 C88 C89 C93 C111 C113-C122 C140 C141 C171-C193 C301 C407 C410 C417 C418 C422 C713 C714 C818 C819 C1001 C1011 C1107 C1202 C1203 C1301-C1316 C1318 C1319 C1322-C1337 C1401-C1403 C1408 C1411 C1434 C1438 C1440 C1601 C1602 C1606-C1611 C1615 C1640-C1643 C1811 C2022 C2023 C2501 C2502 C2516 C2519-C2521 C2523 C2525-C2532 C3011 C3018 C3103 C3105 C3109 C3120 C3127 C3134 C3141 C3403 C3503 C3504 C3509 C3511-C3515 C3525-C3532 = SC0402-PA
C2 C3 C9 C37 C43 C44 C46 C47 C54 C55 C71-C75 C159-C161 C902-C904 C908 C1003-C1005 C2027 C2028 C2033 C3016 C3017 C3019 C3020 C3111 C3119 C3129 C3131 C3143 C3145 C3201-C3203 C3305-C3307 C3310 C3311 C3313 C3505 C3507 C3508 C3519 C3521 C3522 = SC1206-TD
C4 C7 C48 C49 C51 C84-C87 C91 C814-C817 C821 C905-C907 C909-C911 C1441 C1442 C1445 C3007 C3122-C3124 C3136-C3138 C3208-C3210 C3218 = SC0805-TD
C5 = SC0805-TD: signal model: SC0402-PB_10nF
C6 C10 C50 C142 C145 C148 C151 C156 C404 C408 C411 C415 C420 C424 C802 C1505-C1507 C1513-C1515 C1520-C1522 C1527-C1529 C1624-C1626 C2509 C2512 C2514 C2711 C3003 C3110 C3301 C3315 C3506 C3520 = SC0603-TB
C8 C41 C52 C76 C83 C94-C96 C707 C726 C727 C901 C913 C915 C916 C1002 C1106 C1213 C1220 C1426 C1530-C1537 C1628 C1629 C1644 C1801 C1802 C1805 C1812 C2117 C3112 C3132 C3133 C3146 C3147 C3601-C3603 C3611-C3613 = SC0402-PB: signal model: SC0402-PB_10nF
C11 C12 C36 C40 C42 C77 C78 C80 C82 C90 C97-C101 C123 C124 C127 C128 C132-C135 C138 C143 C144 C146 C147 C149 C150 C152 C153 C157 C158 C162 C163 C166-C168 C170 C401 C403 C405 C406 C409 C412 C414 C419 C423 C426 C1012 C1014 C1015 C1101-C1104 C1317 C1320 C1321 C1404-C1407 C1409 C1410 C1412-C1423 C1436 C1437 C1501-C1504 C1509-C1512 C1516-C1519 C1523-C1526 C1620-C1623 C1901 C1904 C1906-C1908 C2026 C2029-C2032 C2034 C2035 C2043 C2044 C2104 C2105 C2107 C2109 C2111 C2114-C2116 C2120 C2122 C2123 C2125-C2128 C2503 C2504 C2811-C2813 C3012 C3104 C3107 C3114 C3212 C3215 C3217 C3220 C3222 C3224 C3225 C3308 C3309 C3407 C3510 C3523 C3604 C3605 C3614-C3617 = SC0402-PB
C13-C31 C33-C35 C601 C603 C604 C607 C608 C619 C620 C711 C717-C719 C731 C820 C835 C836 C839 C1016 C1105 C1108 C1205 C1206 C1208 C1209 C1215 C1217 C1218 C1603-C1605 C1612-C1614 C1617 C1638 C1645-C1647 C1702-C1706 C1708 C1710 C1712 C1806 C1813 C1814 C1816 C1819 C1820 C1822 C1823 C2001-C2021 C2024 C2025 C2103 C2106 C2108 C2110 C2130-C2133 C2202 C2206 C2210 C2301 C2303 C2401 C2403 C2506 C2507 C2510 C2511 C2513 C2515 C2619-C2624 C2633 C2634 C2701-C2703 C2705 C2706 C2712-C2714 C2801 C2803 C2804 C2810 C3102 C3108 C3113 C3121 C3126 C3130 C3135 C3140 C3144 C3213 C3312 C3402 C3404 C3406 C3408 = SC0402-PB: signal model: SC0402-PB_100nF
C32 C39 C154 C155 C402 C413 C416 C421 C425 C605 C606 C609 C610 C621 C622 C706 C834 C1013 C1204 C1211 C1216 C1433 C1435 C1439 C1443 C1616 C1639 C1809 C1818 C1821 C1902 C1903 C1909 C2038-C2040 C2045-C2047 C2112 C2113 C2118 C2121 C2124 C2517 C2518 C2522 C2524 C2704 C3013 C3216 C3223 = SC0603B
C38 C81 C125 C126 C139 C1630-C1637 C3001 C3002 C3005 C3006 C3008-C3010 C3014 C3015 C3106 C3128 C3142 C3302 C3303 C3316 C3501 C3502 C3516-C3518 C3524 C3606 C3607 = SC0603-TC
C56-C70 C1008-C1010 C3115-C3117 = SC1206-TF
C92 C131 C709 C712 C724 C822 C837 C1207 C1210 C1212 C1219 C1424 C1425 C1427-C1432 C1803 C1815 C2505 C2508 C2802 = SC0402-PD
C102-C110 C129 C130 C164 C165 C701 C708 C715 C716 C1201 C2302 C2402 C2909-C2916 C3314 = SC0402
C112 = SCAPC2-0707B
C136 C810 C811 = SC0402-PB: signal model: SC0402_220nF
C137 = SC0402-PD: signal model: SC0402_220nF
C710 C1701 C1707 C1709 C1711 C2921 C3401 = SC0402-PB: signal model: SC0402-PB_10nF*
C722 C723 = SC0402: signal model: SC0402_220nF
C725 = SC0402-PD: signal model: SC0402-PB_10nF
C728 = SC0402-PD: signal model: SC0402-PB_100nF
C1214 C1905 C2036 C2037 C2041 C2042 C2119 C2129 = SC0603-TD
C1508 C1538-C1540 C1627 = SC1206E
C2805-C2809 = SC0603B: signal model: SC0402-PB_100nF
C3004 C3304 = SC0603-TC: signal model: SC0402-PB_100nF
C3101 C3214 = SC0603-TB: signal model: SC0402-PB_10nF
C3610 = SC0402-PA: signal model: SC0402-PB_10nF
D1 D701 D801 = HSD0603-LED
D2 D3 D7-D9 D15 D1701 D1702 D1723-D1725 D2307 D2407 D2408 D2501-D2504 D3301 Q1 Q2 Q4 Q702 Q801 Q1003 Q1107 Q1701-Q1704 Q1803 Q1804 Q1902 Q2901 Q3105 Q3106 Q3304 Q3401 Q3402 Q3502 Q3503 Q3601 Q3602 Q3604-Q3606 = SOT23
D4 = HSOD523
D5 = SD2211
D6 D3501 D3502 = SD3-2618C
D10-D14 D1501-D1504 D1601 = SOP8-50-173
D16 D17 D3302 = SOT23D
D18 D19 D1101 D1102 D3401 = SD1107S
D1703-D1722 D3402 D3601 D3602 = SD1814C
D2201-D2203 D2303 D2305 D2403 D2405 = MLF10B-050-0301L
D3001 = SD1710A
F1001 F3002 = SF2-0302A
F3001 F3301 F3302 F3501 F3502 = SF6127
ICT1 ICT2 = HOLE125
ID1-ID8 = ID-BOARD
J1 J2001 = COPPER0201
J2 = PPWC0304-RF
J3 = SDIM02161-20B
J4 J5 J7 = MOUNT3-2009F
J8 J9 = MB1-1612
J601 = CARD75-2207
J701 = SDIM0226-32
J702 = SSIM0107-50-1927
J803 = CARD75-2208B
J901 = PIDC36-DRF-C
J902 = RWBC0202-165R-A
J903 = PMR0203-165RQ-A
J1501 J1502 J1601 = MJ2-0102SRL-A
J1701 = TB14-138S
J1702 = TB10-138S-A
J1901 = HSDC10-1614B
J2201 J2202 = RUSB9-200-1417A
J2203 = RUSB9-180-0726J
J2301 J2401 = RUSB19-050-1512
J2501 J2502 = VAF6-1406E
J2701 = SED40-32M-H
JP960 = RHOLE168-T244B188
K1701-K1704 = SRLY8-87-224
L1001 L3104 = SL0806B
L1201 = SL0806A
L1401 = SL1008H
L2001 L2101 = SPL0302E
L3001 L3101 = SPL0707N
L3102 L3103 = SPL0404L
LB1-LB10 LB401-LB406 LB802 LB1202 LB1203 LB1401-LB1407 LB2002 LB2201-LB2203 LB2801 LB3001 = SL0402C
LB702 LB703 LB1603-LB1608 LB1610 LB1701-LB1705 LB2001 LB2101 LB2501-LB2509 LB3601-LB3603 = SL0805
LB1601 LB1602 = SL0805-TD
LED3601-LED3603 = SDA4-0606
M1-M7 M15 M23 M24 M27 M28 = HOLE138-M3
M8 M9 = WSA1-1405
M10 M11 = RHOLE168-T244B188B
M12 = HOLE168-T244B188
M13 = HOLE130
M14 = HOLE138E
M16 M17 = HOLE197-315
M18 M25 = HOLE78
M19-M22 = RHOLE189-254
M26 = HOLE177
M3601-M3603 = LG2-1705
Q3 Q1801 Q1802 Q1901 U1001 U2802 = SOT23-3
Q701 Q1001 Q1002 Q1004 Q1105 Q1106 Q2101 Q3101 Q3103 Q3104 Q3201 Q3302 = SOT523-3A
Q1101-Q1104 = RF8-FSC-FDMS86181
Q3001 = RF8-NXP-PSMN1R0
Q3102 Q3202 Q3504 = RF8-TOS-TPCC8105
Q3301 Q3303 Q3501 = SOT-PPAK-8-0303G
R1-R18 R20-R55 R58 R60-R64 R71 R75 R76 R78-R99 R103 R104 R107-R113 R115-R119 R121 R122 R124-R131 R135 R137-R142 R145-R156 R158-R169 R172 R174 R176-R179 R182-R189 R198-R202 R205-R218 R220-R229 R234-R298 R301-R329 R332-R337 R342-R365 R376-R378 R388-R391 R414 R602 R604 R606 R612 R614-R617 R701 R702 R704-R706 R708 R709 R712-R714 R722 R805-R807 R821 R822 R829-R831 R841 R848 R851 R1001-R1007 R1009-R1021 R1030-R1035 R1104-R1107 R1109-R1120 R1201-R1203 R1205-R1222 R1235-R1247 R1310 R1319 R1325 R1328-R1332 R1334 R1351-R1381 R1401-R1403 R1405-R1408 R1501-R1508 R1601 R1606 R1607 R1609-R1613 R1615 R1616 R1619 R1622 R1626-R1630 R1632-R1639 R1641-R1648 R1651 R1652 R1701-R1716 R1801-R1806 R1810-R1822 R1833 R1901 R1907-R1918 R2005-R2012 R2021-R2025 R2030-R2038 R2101-R2103 R2107-R2112 R2121-R2143 R2201-R2231 R2301 R2302 R2305-R2310 R2317 R2401-R2408 R2417 R2503-R2505 R2508-R2512 R2514 R2515 R2517 R2518 R2520 R2521 R2523-R2526 R2623-R2628 R2646 R2647 R2701-R2749 R2754 R2755 R2759 R2760 R2780-R2784 R2803-R2805 R2809-R2811 R2814-R2826 R2828-R2830 R2853-R2866 R2887-R2899 R2932 R2933 R2942 R2943 R2973-R2976 R2983-R2986 R2988 R2990-R2993 R2997 R2999 R3001-R3003 R3006-R3017 R3020-R3023 R3102-R3104 R3106-R3112 R3114-R3123 R3125-R3132 R3134 R3136-R3138 R3201 R3202 R3204-R3206 R3208 R3210 R3211 R3213 R3214 R3216-R3223 R3301-R3310 R3401 R3403-R3416 R3420 R3422-R3426 R3502-R3506 R3536-R3540 R3601-R3609 R3611 R3613-R3621 R3801 = SR0402-TA
R19 R74 R132 R1509-R1512 R1605 R1631 R3004 R3005 = SR0805-TB
R56 R57 R59 R65-R70 R72 R73 R77 R100-R102 R105 R106 R114 R120 R123 R133 R134 R143 R157 R170 R171 R173 R180 R181 R203 R204 R611 R801-R803 R832 R833 R850 R852 R1008 R1022-R1029 R1036 R1101-R1103 R1108 R1223-R1228 R1318 R1320-R1324 R1326 R1333 R1602-R1604 R1608 R1614 R1617 R1618 R1623-R1625 R1640 R1807-R1809 R1823-R1832 R1902-R1906 R2001-R2004 R2026-R2029 R2613-R2618 R2642 R2643 R2750-R2753 R2801 R2802 R2806-R2808 R2812 R2813 R2827 R2831-R2852 R2867-R2876 R2878 R2879 R2881-R2886 R2921-R2923 R2928-R2931 R2934-R2941 R2945-R2949 R2952-R2956 R3105 R3124 R3135 R3203 R3419 = SR0402-TA: signal model: SR0402-TA_33
R136 R144 R190-R196 R299 R300 R330 R331 R392-R401 R1317 = SR0402-TB: signal model: SR0402-TB_2.2
R175 R219 R230-R233 R2013-R2020 R2758 R2761-R2763 R2776-R2779 = SR0402-TA: signal model: SR0402-TA_0
R197 R402-R413 R1301-R1309 R1311-R1316 R1335-R1350 R3113 = SR0402-TB
R1204 R1382 R2513 R2522 = SR0603B
R1620 R1621 R1649 R1650 R2501 R2502 R2506 R2507 R2516 R2519 = SR0603-TB
R3018 R3019 = SR2512B-TF
R3507-R3534 R3541-R3592 = SR2512-TE
RT1 RT2 = SF1913
RV1501 RV1502 RV1601 = SR3-4926B
S3401 S3601 S3602 = RTSW4-RG
SG1 = GND_SINGLE_4
T1 T1602 T2201-T2209 = SL4-0102
T1501-T1504 T1601 = STFM24-40-280
TP1-TP6 TP23 TP24 = TP45_45-SMD
TP7 TP8 = TP50-SMD-OSP
TP9 TP10 = TP2-50-5MIL
TP11 TP12 = GND12
TP13-TP22 TP25 TP26 TP29 TP34 = TP50-SMD
U1 U11 = MLF36A-065-0707L
U2 U7 U8 U12 = SOP4-100-256B
U3 = BGA208-32-1515A
U4 U5 U1604 U2803-U2805 = SOP8-50-154C
U6 = QFP128HG-040-1414L
U9 = BGA153-20-1414A
U10 U1301 = SOP8-20-91C
U13 U14 U701 U1901 U1902 U2205 U2206 = SOT23-6A
U15 U16 U2903 U2904 = MLF24D-050-0604L
U17 = SOP14-26-173C
U301 = MLF64AG-050-0909L
U1002 U2703 = SOP24-26-173A
U1201 = MLF48A-040-0606L
U1401 = MLF7-045-0202L
U1601 = SOP16-26-208-255
U1602 = SOP14-50-150
U1603 = SOP8-50-150B
U2001 U2801 = SOP8-50-208
U2002 = MLF76Q-040-0909L
U2003 U2704 = SOP8-26-118C
U2101 = MLF76L-040-0909L
U2201-U2203 = MLF6C-065-0202L
U2701 = MLF8A-050-0203L
U3001 = SOP10-20-118
U3002 = SOP10-20-124A
U3101 = MLF14A-050-0404L
U3102 U3103 = SOT666-6
U3201 = MLF20J-050-0404L
U3202 = SBAT2-3209
U3401 = SOT23-5
U3402 = SOP8-50-154M
X1 X3 X1201 X1301 X2001 = HSX4-0302B
X2 = SX4-0303K

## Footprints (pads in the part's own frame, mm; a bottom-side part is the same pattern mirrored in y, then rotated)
BGA153-20-1414A
  round 0.254 smd: A1(-3.25,-3.25) A2(-3.25,-2.75) A3(-3.25,-2.25) A4(-3.25,-1.75) A5(-3.25,-1.25) A6(-3.25,-0.75) A7(-3.25,-0.25) A8(-3.25,0.25) A9(-3.25,0.75) A10(-3.25,1.25) A11(-3.25,1.75) A12(-3.25,2.25) A13(-3.25,2.75) A14(-3.25,3.25) B1(-2.75,-3.25) B2(-2.75,-2.75) B3(-2.75,-2.25) B4(-2.75,-1.75) B5(-2.75,-1.25) B6(-2.75,-0.75) B7(-2.75,-0.25) B8(-2.75,0.25) B9(-2.75,0.75) B10(-2.75,1.25) B11(-2.75,1.75) B12(-2.75,2.25) B13(-2.75,2.75) B14(-2.75,3.25) C1(-2.25,-3.25) C2(-2.25,-2.75) C3(-2.25,-2.25) C4(-2.25,-1.75) C5(-2.25,-1.25) C6(-2.25,-0.75) C7(-2.25,-0.25) C8(-2.25,0.25) C9(-2.25,0.75) C10(-2.25,1.25) C11(-2.25,1.75) C12(-2.25,2.25) C13(-2.25,2.75) C14(-2.25,3.25) D1(-1.75,-3.25) D2(-1.75,-2.75) D3(-1.75,-2.25) D4(-1.75,-1.75) D12(-1.75,2.25) D13(-1.75,2.75) D14(-1.75,3.25) E1(-1.25,-3.25) E2(-1.25,-2.75) E3(-1.25,-2.25) E5(-1.25,-1.25) E6(-1.25,-0.75) E7(-1.25,-0.25) E8(-1.25,0.25) E9(-1.25,0.75) E10(-1.25,1.25) E12(-1.25,2.25) E13(-1.25,2.75) E14(-1.25,3.25) F1(-0.75,-3.25) F2(-0.75,-2.75) F3(-0.75,-2.25) F5(-0.75,-1.25) F10(-0.75,1.25) F12(-0.75,2.25) F13(-0.75,2.75) F14(-0.75,3.25) G1(-0.25,-3.25) G2(-0.25,-2.75) G3(-0.25,-2.25) G5(-0.25,-1.25) G10(-0.25,1.25) G12(-0.25,2.25) G13(-0.25,2.75) G14(-0.25,3.25) H1(0.25,-3.25) H2(0.25,-2.75) H3(0.25,-2.25) H5(0.25,-1.25) H10(0.25,1.25) H12(0.25,2.25) H13(0.25,2.75) H14(0.25,3.25) J1(0.75,-3.25) J2(0.75,-2.75) J3(0.75,-2.25) J5(0.75,-1.25) J10(0.75,1.25) J12(0.75,2.25) J13(0.75,2.75) J14(0.75,3.25) K1(1.25,-3.25) K2(1.25,-2.75) K3(1.25,-2.25) K5(1.25,-1.25) K6(1.25,-0.75) K7(1.25,-0.25) K8(1.25,0.25) K9(1.25,0.75) K10(1.25,1.25) K12(1.25,2.25) K13(1.25,2.75) K14(1.25,3.25) L1(1.75,-3.25) L2(1.75,-2.75) L3(1.75,-2.25) L12(1.75,2.25) L13(1.75,2.75) L14(1.75,3.25) M1(2.25,-3.25) M2(2.25,-2.75) M3(2.25,-2.25) M4(2.25,-1.75) M5(2.25,-1.25) M6(2.25,-0.75) M7(2.25,-0.25) M8(2.25,0.25) M9(2.25,0.75) M10(2.25,1.25) M11(2.25,1.75) M12(2.25,2.25) M13(2.25,2.75) M14(2.25,3.25) N1(2.75,-3.25) N2(2.75,-2.75) N3(2.75,-2.25) N4(2.75,-1.75) N5(2.75,-1.25) N6(2.75,-0.75) N7(2.75,-0.25) N8(2.75,0.25) N9(2.75,0.75) N10(2.75,1.25) N11(2.75,1.75) N12(2.75,2.25) N13(2.75,2.75) N14(2.75,3.25) P1(3.25,-3.25) P2(3.25,-2.75) P3(3.25,-2.25) P4(3.25,-1.75) P5(3.25,-1.25) P6(3.25,-0.75) P7(3.25,-0.25) P8(3.25,0.25) P9(3.25,0.75) P10(3.25,1.25) P11(3.25,1.75) P12(3.25,2.25) P13(3.25,2.75) P14(3.25,3.25)
BGA208-32-1515A
  round 0.305 smd: A1(-5.6,-5.6) A2(-5.6,-4.8) A3(-5.6,-4) A4(-5.6,-3.2) A5(-5.6,-2.4) A6(-5.6,-1.6) A7(-5.6,-0.8) A8(-5.6,0) A9(-5.6,0.8) A10(-5.6,1.6) A11(-5.6,2.4) A12(-5.6,3.2) A13(-5.6,4) A14(-5.6,4.8) A15(-5.6,5.6) B1(-4.8,-5.6) B2(-4.8,-4.8) B3(-4.8,-4) B4(-4.8,-3.2) B5(-4.8,-2.4) B6(-4.8,-1.6) B7(-4.8,-0.8) B8(-4.8,0) B9(-4.8,0.8) B10(-4.8,1.6) B11(-4.8,2.4) B12(-4.8,3.2) B13(-4.8,4) B14(-4.8,4.8) B15(-4.8,5.6) C1(-4,-5.6) C2(-4,-4.8) C3(-4,-4) C4(-4,-3.2) C5(-4,-2.4) C6(-4,-1.6) C7(-4,-0.8) C8(-4,0) C9(-4,0.8) C10(-4,1.6) C11(-4,2.4) C12(-4,3.2) C13(-4,4) C14(-4,4.8) C15(-4,5.6) D1(-3.2,-5.6) D2(-3.2,-4.8) D3(-3.2,-4) D4(-3.2,-3.2) D5(-3.2,-2.4) D6(-3.2,-1.6) D7(-3.2,-0.8) D8(-3.2,0) D9(-3.2,0.8) D10(-3.2,1.6) D11(-3.2,2.4) D12(-3.2,3.2) D13(-3.2,4) D14(-3.2,4.8) D15(-3.2,5.6) E1(-2.4,-5.6) E2(-2.4,-4.8) E3(-2.4,-4) E4(-2.4,-3.2) E5(-2.4,-2.4) E6(-2.4,-1.6) E7(-2.4,-0.8) E8(-2.4,0) E9(-2.4,0.8) E10(-2.4,1.6) E11(-2.4,2.4) E12(-2.4,3.2) E13(-2.4,4) E14(-2.4,4.8) E15(-2.4,5.6) F1(-1.6,-5.6) F2(-1.6,-4.8) F3(-1.6,-4) F4(-1.6,-3.2) F5(-1.6,-2.4) F11(-1.6,2.4) F12(-1.6,3.2) F13(-1.6,4) F14(-1.6,4.8) F15(-1.6,5.6) G1(-0.8,-5.6) G2(-0.8,-4.8) G3(-0.8,-4) G4(-0.8,-3.2) G5(-0.8,-2.4) G7(-0.8,-0.8) G8(-0.8,0) G9(-0.8,0.8) G11(-0.8,2.4) G12(-0.8,3.2) G13(-0.8,4) G14(-0.8,4.8) G15(-0.8,5.6) H1(0,-5.6) H2(0,-4.8) H3(0,-4) H4(0,-3.2) H5(0,-2.4) H7(0,-0.8) H9(0,0.8) H11(0,2.4) H12(0,3.2) H13(0,4) H14(0,4.8) H15(0,5.6) J1(0.8,-5.6) J2(0.8,-4.8) J3(0.8,-4) J4(0.8,-3.2) J5(0.8,-2.4) J7(0.8,-0.8) J8(0.8,0) J9(0.8,0.8) J11(0.8,2.4) J12(0.8,3.2) J13(0.8,4) J14(0.8,4.8) J15(0.8,5.6) K1(1.6,-5.6) K2(1.6,-4.8) K3(1.6,-4) K4(1.6,-3.2) K5(1.6,-2.4) K11(1.6,2.4) K12(1.6,3.2) K13(1.6,4) K14(1.6,4.8) K15(1.6,5.6) L1(2.4,-5.6) L2(2.4,-4.8) L3(2.4,-4) L4(2.4,-3.2) L5(2.4,-2.4) L6(2.4,-1.6) L7(2.4,-0.8) L8(2.4,0) L9(2.4,0.8) L10(2.4,1.6) L11(2.4,2.4) L12(2.4,3.2) L13(2.4,4) L14(2.4,4.8) L15(2.4,5.6) M1(3.2,-5.6) M2(3.2,-4.8) M3(3.2,-4) M4(3.2,-3.2) M5(3.2,-2.4) M6(3.2,-1.6) M7(3.2,-0.8) M8(3.2,0) M9(3.2,0.8) M10(3.2,1.6) M11(3.2,2.4) M12(3.2,3.2) M13(3.2,4) M14(3.2,4.8) M15(3.2,5.6) N1(4,-5.6) N2(4,-4.8) N3(4,-4) N4(4,-3.2) N5(4,-2.4) N6(4,-1.6) N7(4,-0.8) N8(4,0) N9(4,0.8) N10(4,1.6) N11(4,2.4) N12(4,3.2) N13(4,4) N14(4,4.8) N15(4,5.6) P1(4.8,-5.6) P2(4.8,-4.8) P3(4.8,-4) P4(4.8,-3.2) P5(4.8,-2.4) P6(4.8,-1.6) P7(4.8,-0.8) P8(4.8,0) P9(4.8,0.8) P10(4.8,1.6) P11(4.8,2.4) P12(4.8,3.2) P13(4.8,4) P14(4.8,4.8) P15(4.8,5.6) R1(5.6,-5.6) R2(5.6,-4.8) R3(5.6,-4) R4(5.6,-3.2) R5(5.6,-2.4) R6(5.6,-1.6) R7(5.6,-0.8) R8(5.6,0) R9(5.6,0.8) R10(5.6,1.6) R11(5.6,2.4) R12(5.6,3.2) R13(5.6,4) R14(5.6,4.8) R15(5.6,5.6)
CARD75-2207
  round 1.092 hole 1.092 unplated: (-10,-1.5)
  round 1.6 hole 1.6 unplated: (10,-1.5)
  rect 0.254x1.422 smd: 1(-9.25,3.149) 2(-9,-3.149) 3(-8.75,3.149) 4(-8.5,-3.149) 5(-8.25,3.149) 6(-8,-3.149) 7(-7.75,3.149) 8(-7.5,-3.149) 9(-7.25,3.149) 10(-7,-3.149) 11(-6.75,3.149) 12(-6.5,-3.149) 13(-6.25,3.149) 14(-6,-3.149) 15(-5.75,3.149) 16(-5.5,-3.149) 17(-5.25,3.149) 18(-5,-3.149) 19(-4.75,3.149) 20(-4.5,-3.149) 21(-4.25,3.149) 22(-4,-3.149) 23(-3.75,3.149) 24(-3.5,-3.149) 25(-3.25,3.149) 26(-3,-3.149) 27(-2.75,3.149) 28(-2.5,-3.149) 29(-2.25,3.149) 30(-2,-3.149) 31(-1.75,3.149) 32(-1.5,-3.149) 33(-1.25,3.149) 34(-1,-3.149) 35(-0.75,3.149) 36(-0.5,-3.149) 37(-0.25,3.149) 38(0,-3.149) 39(0.25,3.149) 40(0.5,-3.149) 41(0.75,3.149) 42(1,-3.149) 43(1.25,3.149) 44(1.5,-3.149) 45(1.75,3.149) 46(2,-3.149) 47(2.25,3.149) 48(2.5,-3.149) 49(2.75,3.149) 50(3,-3.149) 51(3.25,3.149) 52(3.5,-3.149) 53(3.75,3.149) 54(4,-3.149) 55(4.25,3.149) 56(4.5,-3.149) 57(4.75,3.149) 58(5,-3.149) 67(7.25,3.149) 68(7.5,-3.149) 69(7.75,3.149) 70(8,-3.149) 71(8.25,3.149) 72(8.5,-3.149) 73(8.75,3.149) 74(9,-3.149) 75(9.25,3.149)
  round 0 smd: 59(5.25,3.149) 60(5.5,-3.149) 61(5.75,3.149) 62(6,-3.149) 63(6.25,3.149) 64(6.5,-3.149) 65(6.75,3.149) 66(7,-3.149)
  rect 1.219x2.743 smd: 76(-10.35,3) 77(10.35,3)
CARD75-2208B
  round 1.092 hole 1.092 unplated: (-10,-1.525)
  round 1.6 hole 1.6 unplated: (10,-1.525)
  rect 0.254x1.549 smd: 1(-9.25,3.826) 2(-9,-3.876) 3(-8.75,3.826) 4(-8.5,-3.876) 5(-8.25,3.826) 6(-8,-3.876) 7(-7.75,3.826) 8(-7.5,-3.876) 9(-7.25,3.826) 10(-7,-3.876) 11(-6.75,3.826) 20(-4.5,-3.876) 21(-4.25,3.826) 22(-4,-3.876) 23(-3.75,3.826) 24(-3.5,-3.876) 25(-3.25,3.826) 26(-3,-3.876) 27(-2.75,3.826) 28(-2.5,-3.876) 29(-2.25,3.826) 30(-2.001,-3.876) 31(-1.751,3.826) 32(-1.5,-3.876) 33(-1.25,3.826) 34(-1,-3.876) 35(-0.75,3.826) 36(-0.5,-3.876) 37(-0.25,3.826) 38(0,-3.876) 39(0.25,3.826) 40(0.5,-3.876) 41(0.75,3.826) 42(1,-3.876) 43(1.25,3.826) 44(1.5,-3.876) 45(1.75,3.826) 46(2,-3.876) 47(2.25,3.826) 48(2.5,-3.876) 49(2.75,3.826) 50(3,-3.876) 51(3.25,3.826) 52(3.5,-3.876) 53(3.75,3.826) 54(4,-3.876) 55(4.25,3.826) 56(4.5,-3.876) 57(4.75,3.826) 58(5,-3.876) 59(5.25,3.826) 60(5.5,-3.876) 61(5.75,3.826) 62(6,-3.876) 63(6.25,3.826) 64(6.5,-3.876) 65(6.75,3.826) 66(7,-3.876) 67(7.25,3.826) 68(7.5,-3.876) 69(7.75,3.826) 70(8,-3.876) 71(8.25,3.826) 72(8.5,-3.876) 73(8.75,3.826) 74(9,-3.876) 75(9.25,3.826)
  round 0 smd: 12(-6.5,-3.8) 13(-6.25,3.75) 14(-6,-3.8) 15(-5.75,3.75) 16(-5.5,-3.8) 17(-5.25,3.75) 18(-5,-3.8) 19(-4.75,3.75)
  rect 1.219x2.743 smd: 76(-10.35,2.975) 77(10.35,2.975)
COPPER0201
  rect 0.533x0.381 smd: 1(-0.152,0) 2(0.152,0)
GND12
  round 0.635 hole 0.305: 1(0,0)
GND_SINGLE_4
  rect 0.5x0.3 smd: 1(0.1,0)
  round 0.3 smd: 2(0.35,0)
HOLE78
  round 1.981 hole 1.981 unplated: (0,0)
HOLE125
  round 3.175 hole 3.175 unplated: (0,0)
HOLE130
  round 3.302 hole 3.302 unplated: (0,0)
HOLE138-M3
  round 8.001 hole 3.505: 1(0,0)
HOLE138E
  round 3.505 hole 3.505 unplated: (0,0)
HOLE168-T244B188
  round 6.198 hole 4.267: 1(0,0)
HOLE177
  round 4.496 hole 4.496 unplated: (0,0)
HOLE197-315
  round 8.001 hole 5.004: 1(0,0)
HSD0603-LED
  rect 0.762x0.813 smd: 1(-0.737,0) 2(0.737,0)
HSDC10-1614B
  rect 0.711x1.219 smd: 1(2.775,7.975) 2(1.675,7.975) 3(0.575,7.975) 4(-0.525,7.975) 5(-1.625,7.975) 6(-2.725,7.975) 7(-3.825,7.975) 8(-4.925,7.975) 9(-5.891,7.975)
  rect 1.016x1.219 smd: 10(4.325,7.975) 11(-6.825,3.675)
  rect 1.016x0.813 smd: 12(-6.825,-2.526)
  rect 1.016x2.794 smd: 13(-6.825,-6.675)
  rect 1.778x1.905 smd: 14(6.675,-7.125)
HSOD523
  rect 0.356x0.559 smd: 1(0.762,0) 2(-0.762,0)
HSX4-0302B
  rect 1.067x0.965 smd: 1(-0.927,-0.727) 2(0.927,-0.727) 3(0.927,0.727) 4(-0.927,0.727)
ID-BOARD
  round 1.016 smd: 1(0,0)
LG2-1705
  round 2.692 hole 2.692 unplated: (0,0)
  round 2.007 hole 2.007 unplated: (8.4,0)
MB1-1612
  custom 3.65x3.65 hole 5.207: 1(0,0)
MJ2-0102SRL-A
  round 2.794 hole 2.794 unplated: (4.445,-4.2) (20.195,-4.2)
  round 1.27 hole 0.914: 1(0,0) 2(1.27,2.04) 3(2.54,0) 4(3.81,2.04) 5(5.08,0) 6(6.35,2.04) 7(7.62,0) 8(8.89,2.04) 9(15.75,0) 10(17.02,2.04) 11(18.29,0) 12(19.56,2.04) 13(20.83,0) 14(22.1,2.04) 15(23.37,0) 16(24.64,2.04) 17(-2.415,-2.57) 18(0.125,-2.57) 19(8.765,-2.57) 22(15.875,-2.57) 23(24.515,-2.57) 24(27.055,-2.57)
  oval 1.168x1.829 hole 0.914: 20(11.305,-2.57) 21(13.335,-2.57)
  oval 1.524x2.134 hole 1.016x1.626: 25(-3.58,-5.2) 26(-3.58,0.18) 30(28.22,0.18) 31(28.22,-5.2)
  oval 2.134x1.524 hole 1.626x1.016: 27(-2.68,4.3) 28(12.32,4.3) 29(27.32,4.3)
MLF6C-065-0202L
  rect 0.305x0.406 smd: 1(-0.65,-0.953) 2(0,-0.953) 3(0.65,-0.953) 4(0.65,0.953) 5(0,0.953) 6(-0.65,0.953)
  rect 1.651x0.889 smd: 7(0,0)
MLF7-045-0202L
  rect 0.203x0.61 smd: 1(-0.48,-0.655) 2(-0.03,-0.655)
  rect 0.61x0.203 smd: 3(0.655,-0.45) 4(0.655,0) 5(0.655,0.45)
  rect 0.203x1.016 smd: 6(-0.03,0.452) 7(-0.48,0.452)
